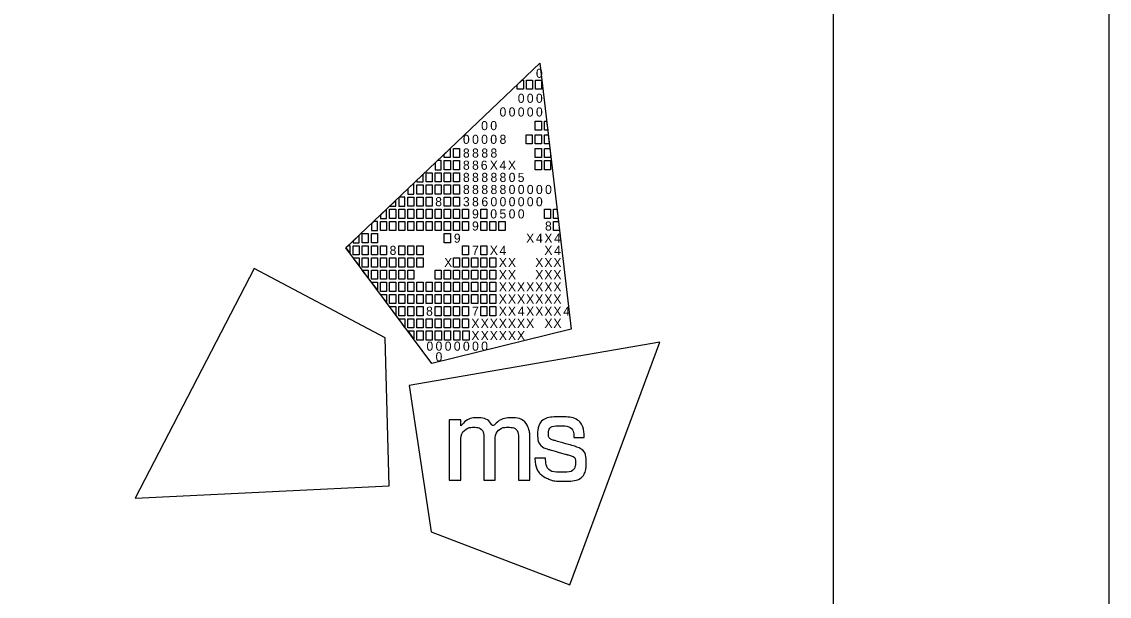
# Model space of a CAD drawing. Extents: x -6.8 to 34, y 0 to 22.
# Drawn here: x 32.03 to 34, y 3.122 to 4.161 of the extents above; entities that cross this region are included whole.
import ezdxf

# ---------------------------------------------------------------- set-up
doc = ezdxf.new("R2010")
doc.units = 0
for name, color, linetype in [('SH_Border', 7, 'Continuous'), ('SH_Cut_Line', 7, 'Continuous'), ('SH_Data', 7, 'Continuous')]:
    doc.layers.add(name, color=color, linetype=linetype)

msp = doc.modelspace()

# ---------------------------------------------------------------- linework, layer by layer
at = {"layer": 'SH_Border'}
for p, q in [((32.6175, 3.7519), (32.9688, 4.0861)), ((32.9688, 4.0861), (32.9688, 4.0861)), ((32.9688, 4.0861), (33.0253, 3.6052)), ((32.773, 3.543), (32.6175, 3.7519)), ((33.0253, 3.6052), (32.773, 3.543))]:
    msp.add_line(p, q, dxfattribs=at)
for points in [[(1.5, 21.5), (33.5, 21.5), (33.5, 0.5), (1.5, 0.5)], [(32.9279, 4.0472), (32.9369, 4.0558), (32.9389, 4.0558), (32.9389, 4.0393), (32.9279, 4.0393)], [(32.9444, 4.0558), (32.9554, 4.0558), (32.9554, 4.0393), (32.9444, 4.0393)], [(32.9609, 4.0558), (32.9719, 4.0558), (32.9719, 4.0393), (32.9609, 4.0393)], [(32.9606, 3.9815), (32.9716, 3.9815), (32.9716, 3.965), (32.9606, 3.965)], [(32.9771, 3.9815), (32.9811, 3.9815), (32.983, 3.965), (32.9771, 3.965)], [(32.9441, 3.9567), (32.9551, 3.9567), (32.9551, 3.9402), (32.9441, 3.9402)], [(32.9606, 3.9567), (32.9716, 3.9567), (32.9716, 3.9402), (32.9606, 3.9402)], [(32.9771, 3.9567), (32.984, 3.9567), (32.9859, 3.9402), (32.9771, 3.9402)], [(32.7953, 3.9211), (32.8064, 3.9316), (32.8064, 3.9154), (32.7953, 3.9154)], [(32.8123, 3.9319), (32.8233, 3.9319), (32.8233, 3.9154), (32.8123, 3.9154)], [(32.9606, 3.9319), (32.9716, 3.9319), (32.9716, 3.9154), (32.9606, 3.9154)], [(32.9771, 3.9319), (32.9869, 3.9319), (32.9881, 3.9218), (32.9881, 3.9154), (32.9771, 3.9154)], [(32.7958, 3.9099), (32.8068, 3.9099), (32.8068, 3.8934), (32.7958, 3.8934)], [(32.8123, 3.9099), (32.8233, 3.9099), (32.8233, 3.8934), (32.8123, 3.8934)], [(32.9606, 3.9099), (32.9716, 3.9099), (32.9716, 3.8934), (32.9606, 3.8934)], [(32.9771, 3.9099), (32.9881, 3.9099), (32.9881, 3.8934), (32.9771, 3.8934)], [(32.7627, 3.8879), (32.7737, 3.8879), (32.7737, 3.8714), (32.7627, 3.8714)], [(32.7793, 3.8879), (32.7903, 3.8879), (32.7903, 3.8714), (32.7793, 3.8714)], [(32.7958, 3.8879), (32.8068, 3.8879), (32.8068, 3.8714), (32.7958, 3.8714)], [(32.8123, 3.8879), (32.8233, 3.8879), (32.8233, 3.8714), (32.8123, 3.8714)], [(32.7462, 3.8659), (32.7572, 3.8659), (32.7572, 3.8494), (32.7462, 3.8494)], [(32.7627, 3.8659), (32.7737, 3.8659), (32.7737, 3.8494), (32.7627, 3.8494)], [(32.7793, 3.8659), (32.7903, 3.8659), (32.7903, 3.8494), (32.7793, 3.8494)], [(32.7958, 3.8659), (32.8068, 3.8659), (32.8068, 3.8494), (32.7958, 3.8494)], [(32.8123, 3.8659), (32.8233, 3.8659), (32.8233, 3.8494), (32.8123, 3.8494)], [(32.7297, 3.8439), (32.7407, 3.8439), (32.7407, 3.8273), (32.7297, 3.8273)], [(32.7462, 3.8439), (32.7572, 3.8439), (32.7572, 3.8273), (32.7462, 3.8273)], [(32.7627, 3.8439), (32.7737, 3.8439), (32.7737, 3.8273), (32.7627, 3.8273)], [(32.7958, 3.8439), (32.8068, 3.8439), (32.8068, 3.8273), (32.7958, 3.8273)], [(32.8123, 3.8439), (32.8233, 3.8439), (32.8233, 3.8273), (32.8123, 3.8273)], [(32.6967, 3.8218), (32.7077, 3.8218), (32.7077, 3.8053), (32.6967, 3.8053)], [(32.7132, 3.8218), (32.7242, 3.8218), (32.7242, 3.8053), (32.7132, 3.8053)], [(32.7297, 3.8218), (32.7407, 3.8218), (32.7407, 3.8053), (32.7297, 3.8053)], [(32.7462, 3.8218), (32.7572, 3.8218), (32.7572, 3.8053), (32.7462, 3.8053)], [(32.7627, 3.8218), (32.7737, 3.8218), (32.7737, 3.8053), (32.7627, 3.8053)], [(32.7793, 3.8218), (32.7903, 3.8218), (32.7903, 3.8053), (32.7793, 3.8053)], [(32.7958, 3.8218), (32.8068, 3.8218), (32.8068, 3.8053), (32.7958, 3.8053)], [(32.8123, 3.8218), (32.8233, 3.8218), (32.8233, 3.8053), (32.8123, 3.8053)], [(32.8288, 3.8218), (32.8398, 3.8218), (32.8398, 3.8053), (32.8288, 3.8053)], [(32.8618, 3.8218), (32.8728, 3.8218), (32.8728, 3.8053), (32.8618, 3.8053)], [(32.9771, 3.8218), (32.9881, 3.8218), (32.9881, 3.8053), (32.9771, 3.8053)], [(32.9935, 3.8218), (32.9998, 3.8218), (33.0018, 3.8053), (32.9935, 3.8053)], [(32.6802, 3.7998), (32.6912, 3.7998), (32.6912, 3.7833), (32.6802, 3.7833)], [(32.6967, 3.7998), (32.7077, 3.7998), (32.7077, 3.7833), (32.6967, 3.7833)], [(32.7132, 3.7998), (32.7242, 3.7998), (32.7242, 3.7833), (32.7132, 3.7833)], [(32.7297, 3.7998), (32.7407, 3.7998), (32.7407, 3.7833), (32.7297, 3.7833)], [(32.7462, 3.7998), (32.7572, 3.7998), (32.7572, 3.7833), (32.7462, 3.7833)], [(32.7627, 3.7998), (32.7737, 3.7998), (32.7737, 3.7833), (32.7627, 3.7833)], [(32.7793, 3.7998), (32.7903, 3.7998), (32.7903, 3.7833), (32.7793, 3.7833)], [(32.7958, 3.7998), (32.8068, 3.7998), (32.8068, 3.7833), (32.7958, 3.7833)], [(32.8123, 3.7998), (32.8233, 3.7998), (32.8233, 3.7833), (32.8123, 3.7833)], [(32.8288, 3.7998), (32.8398, 3.7998), (32.8398, 3.7833), (32.8288, 3.7833)], [(32.8618, 3.7998), (32.8728, 3.7998), (32.8728, 3.7833), (32.8618, 3.7833)], [(32.8783, 3.7998), (32.8893, 3.7998), (32.8893, 3.7833), (32.8783, 3.7833)], [(32.8947, 3.7998), (32.9057, 3.7998), (32.9057, 3.7833), (32.8947, 3.7833)], [(32.9935, 3.7998), (33.0024, 3.7998), (33.0044, 3.7833), (32.9935, 3.7833)], [(32.6471, 3.7778), (32.6581, 3.7778), (32.6581, 3.7613), (32.6471, 3.7613)], [(32.6637, 3.7778), (32.6747, 3.7778), (32.6747, 3.7613), (32.6637, 3.7613)], [(32.7958, 3.7778), (32.8068, 3.7778), (32.8068, 3.7613), (32.7958, 3.7613)], [(32.6306, 3.7558), (32.6416, 3.7558), (32.6416, 3.7393), (32.6306, 3.7393)], [(32.6471, 3.7558), (32.6581, 3.7558), (32.6581, 3.7393), (32.6471, 3.7393)], [(32.6637, 3.7558), (32.6747, 3.7558), (32.6747, 3.7393), (32.6637, 3.7393)], [(32.6802, 3.7558), (32.6912, 3.7558), (32.6912, 3.7393), (32.6802, 3.7393)], [(32.7132, 3.7558), (32.7242, 3.7558), (32.7242, 3.7393), (32.7132, 3.7393)], [(32.7297, 3.7558), (32.7407, 3.7558), (32.7407, 3.7393), (32.7297, 3.7393)], [(32.7462, 3.7558), (32.7572, 3.7558), (32.7572, 3.7393), (32.7462, 3.7393)], [(32.8288, 3.7558), (32.8398, 3.7558), (32.8398, 3.7393), (32.8288, 3.7393)], [(32.8618, 3.7558), (32.8728, 3.7558), (32.8728, 3.7393), (32.8618, 3.7393)], [(32.6306, 3.7338), (32.6416, 3.7338), (32.6416, 3.72)], [(32.6471, 3.7338), (32.6581, 3.7338), (32.6581, 3.7173), (32.6471, 3.7173)], [(32.6637, 3.7338), (32.6747, 3.7338), (32.6747, 3.7173), (32.6637, 3.7173)], [(32.6802, 3.7338), (32.6912, 3.7338), (32.6912, 3.7173), (32.6802, 3.7173)], [(32.6967, 3.7338), (32.7077, 3.7338), (32.7077, 3.7173), (32.6967, 3.7173)], [(32.7132, 3.7338), (32.7242, 3.7338), (32.7242, 3.7173), (32.7132, 3.7173)], [(32.7297, 3.7338), (32.7407, 3.7338), (32.7407, 3.7173), (32.7297, 3.7173)], [(32.7462, 3.7338), (32.7572, 3.7338), (32.7572, 3.7173), (32.7462, 3.7173)], [(32.8123, 3.7338), (32.8233, 3.7338), (32.8233, 3.7173), (32.8123, 3.7173)], [(32.8288, 3.7338), (32.8398, 3.7338), (32.8398, 3.7173), (32.8288, 3.7173)], [(32.8453, 3.7338), (32.8563, 3.7338), (32.8563, 3.7173), (32.8453, 3.7173)], [(32.8618, 3.7338), (32.8728, 3.7338), (32.8728, 3.7173), (32.8618, 3.7173)], [(32.8783, 3.7338), (32.8893, 3.7338), (32.8893, 3.7173), (32.8783, 3.7173)], [(32.6471, 3.7117), (32.6581, 3.7117), (32.6581, 3.698)], [(32.6637, 3.7117), (32.6747, 3.7117), (32.6747, 3.6952), (32.6637, 3.6952)], [(32.6802, 3.7117), (32.6912, 3.7117), (32.6912, 3.6952), (32.6802, 3.6952)], [(32.6967, 3.7117), (32.7077, 3.7117), (32.7077, 3.6952), (32.6967, 3.6952)], [(32.7132, 3.7117), (32.7242, 3.7117), (32.7242, 3.6952), (32.7132, 3.6952)], [(32.7297, 3.7117), (32.7407, 3.7117), (32.7407, 3.6952), (32.7297, 3.6952)], [(32.7793, 3.7117), (32.7903, 3.7117), (32.7903, 3.6952), (32.7793, 3.6952)], [(32.7958, 3.7117), (32.8068, 3.7117), (32.8068, 3.6952), (32.7958, 3.6952)], [(32.8123, 3.7117), (32.8233, 3.7117), (32.8233, 3.6952), (32.8123, 3.6952)], [(32.8288, 3.7117), (32.8398, 3.7117), (32.8398, 3.6952), (32.8288, 3.6952)], [(32.8453, 3.7117), (32.8563, 3.7117), (32.8563, 3.6952), (32.8453, 3.6952)], [(32.8618, 3.7117), (32.8728, 3.7117), (32.8728, 3.6952), (32.8618, 3.6952)], [(32.8783, 3.7117), (32.8893, 3.7117), (32.8893, 3.6952), (32.8783, 3.6952)], [(32.6637, 3.6897), (32.6747, 3.6897), (32.6747, 3.676)], [(32.6747, 3.6897), (32.6747, 3.6897), (32.6747, 3.6897)], [(32.6802, 3.6897), (32.6912, 3.6897), (32.6912, 3.6732), (32.6802, 3.6732)], [(32.6967, 3.6897), (32.7077, 3.6897), (32.7077, 3.6732), (32.6967, 3.6732)], [(32.7132, 3.6897), (32.7242, 3.6897), (32.7242, 3.6732), (32.7132, 3.6732)], [(32.7297, 3.6897), (32.7407, 3.6897), (32.7407, 3.6732), (32.7297, 3.6732)], [(32.7462, 3.6897), (32.7572, 3.6897), (32.7572, 3.6732), (32.7462, 3.6732)], [(32.7627, 3.6897), (32.7737, 3.6897), (32.7737, 3.6732), (32.7627, 3.6732)], [(32.7793, 3.6897), (32.7903, 3.6897), (32.7903, 3.6732), (32.7793, 3.6732)], [(32.7958, 3.6897), (32.8068, 3.6897), (32.8068, 3.6732), (32.7958, 3.6732)], [(32.8123, 3.6897), (32.8233, 3.6897), (32.8233, 3.6732), (32.8123, 3.6732)], [(32.8288, 3.6897), (32.8398, 3.6897), (32.8398, 3.6732), (32.8288, 3.6732)], [(32.8453, 3.6897), (32.8563, 3.6897), (32.8563, 3.6732), (32.8453, 3.6732)], [(32.8618, 3.6897), (32.8728, 3.6897), (32.8728, 3.6732), (32.8618, 3.6732)], [(32.8783, 3.6897), (32.8893, 3.6897), (32.8893, 3.6732), (32.8783, 3.6732)], [(32.6802, 3.6677), (32.6912, 3.6677), (32.6912, 3.654)], [(32.6967, 3.6677), (32.7077, 3.6677), (32.7077, 3.6512), (32.6967, 3.6512)], [(32.7132, 3.6677), (32.7242, 3.6677), (32.7242, 3.6512), (32.7132, 3.6512)], [(32.7297, 3.6677), (32.7407, 3.6677), (32.7407, 3.6512), (32.7297, 3.6512)], [(32.7462, 3.6677), (32.7572, 3.6677), (32.7572, 3.6512), (32.7462, 3.6512)], [(32.7627, 3.6677), (32.7737, 3.6677), (32.7737, 3.6512), (32.7627, 3.6512)], [(32.7793, 3.6677), (32.7903, 3.6677), (32.7903, 3.6512), (32.7793, 3.6512)], [(32.7958, 3.6677), (32.8068, 3.6677), (32.8068, 3.6512), (32.7958, 3.6512)], [(32.8123, 3.6677), (32.8233, 3.6677), (32.8233, 3.6512), (32.8123, 3.6512)], [(32.8288, 3.6677), (32.8398, 3.6677), (32.8398, 3.6512), (32.8288, 3.6512)], [(32.8453, 3.6677), (32.8563, 3.6677), (32.8563, 3.6512), (32.8453, 3.6512)], [(32.8618, 3.6677), (32.8728, 3.6677), (32.8728, 3.6512), (32.8618, 3.6512)], [(32.8783, 3.6677), (32.8893, 3.6677), (32.8893, 3.6512), (32.8783, 3.6512)], [(32.7077, 3.6305), (32.6965, 3.6457), (32.7077, 3.6457)], [(32.7132, 3.6457), (32.7242, 3.6457), (32.7242, 3.6292), (32.7132, 3.6292)], [(32.7297, 3.6457), (32.7407, 3.6457), (32.7407, 3.6292), (32.7297, 3.6292)], [(32.7462, 3.6457), (32.7572, 3.6457), (32.7572, 3.6292), (32.7462, 3.6292)], [(32.7793, 3.6457), (32.7903, 3.6457), (32.7903, 3.6292), (32.7793, 3.6292)], [(32.7958, 3.6457), (32.8068, 3.6457), (32.8068, 3.6292), (32.7958, 3.6292)], [(32.8123, 3.6457), (32.8233, 3.6457), (32.8233, 3.6292), (32.8123, 3.6292)], [(32.8288, 3.6457), (32.8398, 3.6457), (32.8398, 3.6292), (32.8288, 3.6292)], [(32.8618, 3.6457), (32.8728, 3.6457), (32.8728, 3.6292), (32.8618, 3.6292)], [(32.8783, 3.6457), (32.8893, 3.6457), (32.8893, 3.6292), (32.8783, 3.6292)], [(32.724, 3.6082), (32.7132, 3.6237), (32.7242, 3.6237)], [(32.7297, 3.6237), (32.7407, 3.6237), (32.7407, 3.6072), (32.7297, 3.6072)], [(32.7462, 3.6237), (32.7572, 3.6237), (32.7572, 3.6072), (32.7462, 3.6072)], [(32.7627, 3.6237), (32.7737, 3.6237), (32.7737, 3.6072), (32.7627, 3.6072)], [(32.7793, 3.6237), (32.7903, 3.6237), (32.7903, 3.6072), (32.7793, 3.6072)], [(32.7958, 3.6237), (32.8068, 3.6237), (32.8068, 3.6072), (32.7958, 3.6072)], [(32.8123, 3.6237), (32.8233, 3.6237), (32.8233, 3.6072), (32.8123, 3.6072)], [(32.8288, 3.6237), (32.8398, 3.6237), (32.8398, 3.6072), (32.8288, 3.6072)], [(32.7302, 3.6017), (32.7407, 3.6017), (32.7408, 3.5875)], [(32.7463, 3.6017), (32.7573, 3.6017), (32.7573, 3.5852), (32.7463, 3.5852)], [(32.763, 3.6017), (32.774, 3.6017), (32.774, 3.5852), (32.763, 3.5852)], [(32.7794, 3.6017), (32.7904, 3.6017), (32.7904, 3.5852), (32.7794, 3.5852)], [(32.796, 3.6017), (32.807, 3.6017), (32.807, 3.5852), (32.796, 3.5852)], [(32.8129, 3.6017), (32.8239, 3.6017), (32.8239, 3.5851), (32.8129, 3.5851)], [(32.8296, 3.6017), (32.8406, 3.6017), (32.8406, 3.5851), (32.8296, 3.5851)]]:
    msp.add_lwpolyline(points, close=True, dxfattribs=at)
for points in [[(32.7903, 3.9099), (32.7836, 3.9099), (32.7793, 3.9058), (32.7793, 3.8934), (32.7903, 3.8934), (32.7903, 3.9099)], [(32.7572, 3.8849), (32.7462, 3.8744), (32.7462, 3.8714), (32.7572, 3.8714), (32.7572, 3.8849)], [(32.7407, 3.8691), (32.7297, 3.8587), (32.7297, 3.8494), (32.7407, 3.8494), (32.7407, 3.8691)], [(32.7242, 3.8439), (32.7141, 3.8439), (32.7132, 3.843), (32.7132, 3.8273), (32.7242, 3.8273), (32.7242, 3.8439)], [(32.6912, 3.822), (32.6802, 3.8115), (32.6802, 3.8053), (32.6912, 3.8053), (32.6912, 3.822)], [(32.7077, 3.8377), (32.6968, 3.8273), (32.7077, 3.8273), (32.7077, 3.8377)], [(32.6747, 3.7998), (32.6679, 3.7998), (32.6637, 3.7958), (32.6637, 3.7833), (32.6747, 3.7833), (32.6747, 3.7998)], [(32.6416, 3.7749), (32.6306, 3.7644), (32.6306, 3.7613), (32.6416, 3.7613), (32.6416, 3.7749)], [(32.6251, 3.7558), (32.6216, 3.7558), (32.6175, 3.7519), (32.6251, 3.7417), (32.6251, 3.7558)], [(32.4512, 3.7149), (32.2359, 3.2988), (32.6956, 3.3215), (32.6884, 3.5892), (32.4512, 3.7149)], [(33.0229, 3.1422), (33.1859, 3.5814), (32.7324, 3.5029), (32.7722, 3.2381), (33.0229, 3.1422)]]:
    msp.add_lwpolyline(points, dxfattribs=at)
for points in [[(32.8048, 3.3315), (32.8048, 3.3315), (32.8048, 3.4409), (32.8048, 3.4409), (32.8048, 3.4409), (32.8255, 3.4409), (32.8255, 3.4409), (32.8255, 3.4409), (32.8255, 3.4297), (32.8255, 3.4297), (32.8346, 3.4399), (32.8457, 3.4445), (32.8555, 3.4445), (32.8688, 3.4445), (32.8791, 3.4372), (32.8837, 3.4266), (32.8915, 3.4381), (32.905, 3.4446), (32.9166, 3.4446), (32.9325, 3.4446), (32.9451, 3.435), (32.9494, 3.4213), (32.9494, 3.4212), (32.9494, 3.4212), (32.9494, 3.4212), (32.9501, 3.419), (32.9506, 3.4172), (32.9506, 3.4071), (32.9506, 3.4071), (32.9506, 3.3314), (32.9506, 3.3314), (32.9506, 3.3314), (32.9303, 3.3314), (32.9303, 3.3314), (32.9303, 3.3314), (32.9303, 3.4048), (32.9303, 3.4048), (32.9303, 3.4201), (32.9219, 3.4274), (32.911, 3.4274), (32.8995, 3.4274), (32.8879, 3.4171), (32.8879, 3.4001), (32.8879, 3.4001), (32.8879, 3.3315), (32.8879, 3.3315), (32.8879, 3.3315), (32.8674, 3.3315), (32.8674, 3.3315), (32.8674, 3.3315), (32.8674, 3.4059), (32.8674, 3.4059), (32.8674, 3.4203), (32.8588, 3.4274), (32.8496, 3.4274), (32.8384, 3.4274), (32.8254, 3.417), (32.8254, 3.3962), (32.8254, 3.3962), (32.8254, 3.3315), (32.8254, 3.3315), (32.8254, 3.3315), (32.8048, 3.3315), (32.8048, 3.3315)], [(32.9595, 3.3709), (32.9595, 3.3709), (32.9595, 3.3717), (32.9595, 3.3717), (32.9595, 3.3717), (32.9603, 3.3717), (32.9603, 3.3717), (32.9603, 3.3717), (32.9783, 3.3717), (32.9783, 3.3717), (32.9783, 3.3717), (32.9789, 3.3717), (32.9789, 3.3717), (32.9789, 3.3717), (32.979, 3.371), (32.979, 3.371), (32.9803, 3.3554), (32.9887, 3.346), (33.009, 3.346), (33.0273, 3.346), (33.0333, 3.3554), (33.0333, 3.3631), (33.0333, 3.3732), (33.0256, 3.3758), (33.0175, 3.378), (33.0175, 3.378), (32.987, 3.3867), (32.987, 3.3867), (32.972, 3.3909), (32.9648, 3.4019), (32.9648, 3.4142), (32.9648, 3.4303), (32.9768, 3.4462), (33.0052, 3.4462), (33.0348, 3.4462), (33.0489, 3.4285), (33.0489, 3.4095), (33.0489, 3.4095), (33.0489, 3.4087), (33.0489, 3.4087), (33.0489, 3.4087), (33.0482, 3.4087), (33.0482, 3.4087), (33.0482, 3.4087), (33.0312, 3.4087), (33.0312, 3.4087), (33.0312, 3.4087), (33.0305, 3.4087), (33.0305, 3.4087), (33.0305, 3.4087), (33.0305, 3.4094), (33.0305, 3.4094), (33.0301, 3.4208), (33.0226, 3.43), (33.0056, 3.43), (32.9891, 3.43), (32.9843, 3.4218), (32.9843, 3.4157), (32.9843, 3.4108), (32.9869, 3.4059), (32.9959, 3.4033), (32.9959, 3.4033), (33.0255, 3.3948), (33.0255, 3.3948), (33.0462, 3.3889), (33.0527, 3.3777), (33.0527, 3.3639), (33.0527, 3.3462), (33.041, 3.3298), (33.0087, 3.3298), (32.9952, 3.3298), (32.9877, 3.3321), (32.9823, 3.3348), (32.969, 3.3414), (32.9609, 3.3536), (32.9595, 3.3709)]]:
    msp.add_open_spline(points, degree=3, dxfattribs=at)
at = {"layer": 'SH_Cut_Line'}
msp.add_lwpolyline([(0, 0), (34, 0), (34, 22), (0, 22)], close=True, dxfattribs=at)
at = {"layer": 'SH_Data'}
msp.add_line((32.75, 3.5), (32.75, 3.5), dxfattribs=at)

# ---------------------------------------------------------------- texts
at = {"layer": 'SH_Border'}
for s, p in [('0', (32.9617, 4.0597)), ('0', (32.9288, 4.0145)), ('0', (32.9452, 4.0145)), ('0', (32.9617, 4.0145)), ('0', (32.8958, 3.9897)), ('0', (32.9123, 3.9897)), ('0', (32.9288, 3.9897)), ('0', (32.9452, 3.9897)), ('0', (32.9617, 3.9897)), ('0', (32.8625, 3.965)), ('0', (32.879, 3.965)), ('0', (32.8295, 3.9402)), ('0', (32.846, 3.9402)), ('0', (32.8625, 3.9402)), ('0', (32.879, 3.9402)), ('8', (32.8958, 3.9402)), ('8', (32.8295, 3.9154)), ('8', (32.846, 3.9154)), ('8', (32.8628, 3.9154)), ('8', (32.8793, 3.9154)), ('8', (32.8295, 3.8934)), ('8', (32.846, 3.8934)), ('6', (32.8618, 3.8934)), ('X', (32.8781, 3.8934)), ('4', (32.8958, 3.8934)), ('X', (32.911, 3.8934)), ('8', (32.8295, 3.8713)), ('8', (32.846, 3.8713)), ('8', (32.8628, 3.8713)), ('8', (32.8794, 3.8713)), ('8', (32.8958, 3.8713)), ('0', (32.9123, 3.8713)), ('5', (32.9287, 3.8713)), ('8', (32.8295, 3.8494)), ('8', (32.846, 3.8494)), ('8', (32.8628, 3.8494)), ('8', (32.8794, 3.8494)), ('8', (32.8958, 3.8494)), ('0', (32.9123, 3.8494)), ('0', (32.9288, 3.8494)), ('0', (32.9452, 3.8494)), ('0', (32.9617, 3.8494)), ('0', (32.9782, 3.8494)), ('8', (32.7793, 3.8273)), ('3', (32.8295, 3.8273)), ('8', (32.846, 3.8273)), ('6', (32.8629, 3.8273)), ('0', (32.8793, 3.8273)), ('0', (32.8958, 3.8273)), ('0', (32.9123, 3.8273)), ('0', (32.9288, 3.8273)), ('0', (32.9452, 3.8273)), ('0', (32.9617, 3.8273)), ('9', (32.846, 3.8053)), ('0', (32.879, 3.8053)), ('5', (32.8957, 3.8053)), ('0', (32.9123, 3.8053)), ('0', (32.9288, 3.8053)), ('9', (32.846, 3.7833)), ('8', (32.9781, 3.7833)), ('9', (32.813, 3.7613)), ('X', (32.9439, 3.7613)), ('4', (32.9617, 3.7613)), ('X', (32.9769, 3.7613)), ('4', (32.9946, 3.7613)), ('8', (32.6967, 3.7393)), ('7', (32.846, 3.7393)), ('X', (32.8781, 3.7393)), ('4', (32.8958, 3.7393)), ('X', (32.9769, 3.7393)), ('4', (32.9946, 3.7393)), ('X', (32.7955, 3.7173)), ('X', (32.8945, 3.7173)), ('X', (32.911, 3.7173)), ('X', (32.9604, 3.7173)), ('X', (32.9769, 3.7173)), ('X', (32.9933, 3.7173)), ('X', (32.8945, 3.6952)), ('X', (32.911, 3.6952)), ('X', (32.9604, 3.6952)), ('X', (32.9769, 3.6952)), ('X', (32.9933, 3.6952)), ('X', (32.8945, 3.6732)), ('X', (32.911, 3.6732)), ('X', (32.9274, 3.6732)), ('X', (32.9439, 3.6732)), ('X', (32.9604, 3.6732)), ('X', (32.9769, 3.6732)), ('X', (32.9933, 3.6732)), ('X', (32.8945, 3.6512)), ('X', (32.911, 3.6512)), ('X', (32.9274, 3.6512)), ('X', (32.9439, 3.6512)), ('X', (32.9604, 3.6512)), ('X', (32.9769, 3.6512)), ('X', (32.9933, 3.6512)), ('8', (32.7627, 3.6292)), ('7', (32.846, 3.6292)), ('X', (32.8945, 3.6292)), ('X', (32.911, 3.6292)), ('4', (32.9288, 3.6292)), ('X', (32.9439, 3.6292)), ('X', (32.9604, 3.6292)), ('X', (32.9769, 3.6292)), ('X', (32.9933, 3.6292)), ('4', (33.0111, 3.6292)), ('X', (32.8447, 3.6072)), ('X', (32.8616, 3.6072)), ('X', (32.878, 3.6072)), ('X', (32.8945, 3.6072)), ('X', (32.911, 3.6072)), ('X', (32.9274, 3.6072)), ('X', (32.9439, 3.6072)), ('X', (32.9771, 3.6072)), ('X', (32.9933, 3.6072)), ('X', (32.8447, 3.5851)), ('X', (32.8616, 3.5851)), ('X', (32.878, 3.5851)), ('X', (32.8945, 3.5851)), ('X', (32.911, 3.5851)), ('X', (32.9274, 3.5851)), ('0', (32.7634, 3.5659)), ('0', (32.7799, 3.5659)), ('0', (32.7965, 3.5659)), ('0', (32.813, 3.5659)), ('0', (32.8295, 3.5659)), ('0', (32.846, 3.5659)), ('0', (32.8625, 3.5659)), ('0', (32.7799, 3.5467))]:
    msp.add_text(s, height=0.0165, rotation=360, dxfattribs=at).set_placement(p)

doc.saveas('drawing.dxf')
